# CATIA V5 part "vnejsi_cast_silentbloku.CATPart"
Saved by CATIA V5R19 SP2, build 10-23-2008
Part number: vnejsi_cast_silentbloku
Bounding box of the stored display mesh (mm): x -44.987 to 44.987, y -34 to 34, z -44.987 to 44.987
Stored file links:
  D:\Catia fórum\Modely - Otazky\Naklapeni_oprava\vnejsi_cast_silentbloku.CATPart
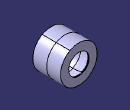
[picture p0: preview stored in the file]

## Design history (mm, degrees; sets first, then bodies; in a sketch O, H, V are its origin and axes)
Body1 (main body)
  Sketch1 on yz-plane, origin (0, 0, 0), H (0, 1, 0), V (0, 0, 1)
    axis line L1 (-49.7859, 0) -> (129.8264, 0)
    point P1 (-49.7859, 0)
    construction line L2 (0, 59.2551) -> (0, -50.8447)
    point P3 (0, 59.2551)
    line L3 (-34, 45) -> (0, 45)
    line L4 (-34, 45) -> (-34, 25)
    point P5 (-34, 45)
    arc A1 centre (0, 0) radius 40 from (0, 40) to (-30.3575, 26.0465) ccw
    point P6 (0, 40)
    point P7 (0, 45)
    line L5 (-34, 25) -> (-32.6343, 25)
    arc A2 centre (-32.6343, 28) radius 3 from (-30.3575, 26.0465) to (-32.6343, 25) cw
    point P8 (-30.3575, 26.0465)
    point P9 (-32.6343, 25)
    point P11 (-34, 25)
    point P12 (34, 45)
    point P13 (30.3575, 26.0465)
    point P14 (32.6343, 25)
    point P16 (34, 25)
    line L6 (34, 45) -> (34, 25)
    line L7 (34, 25) -> (32.6343, 25)
    arc A3 centre (32.6343, 28) radius 3 from (30.3575, 26.0465) to (32.6343, 25) ccw
    point P17 (0, 45)
    line L8 (34, 45) -> (0, 45)
    point P18 (0, 40)
    arc A4 centre (0, 0) radius 40 from (0, 40) to (30.3575, 26.0465) cw
    distance L3 L1 = 45
    distance L4 L2 = 34
    radius A1 = 40
    distance L5 L1 = 25
    radius A2 = 3
    coincidence: P1 H, P3 V, L2 P6, L2 P7, P6 P18, P7 P17
    horizontal: L1 H, L3 H, L5 H
    vertical: L2 V, L4 V
    tangency: A2 A1, A2 L5
    symmetry: P5 P12 L2, P8 P13 L2, P9 P14 L2, P11 P16 L2, L4 L6 L2, L5 L7 L2, A2 A3 L2, P7 P17 L2, L3 L8 L2, P6 P18 L2, A1 A4 L2
  Shaft1: profile Sketch1, axis Sketch1.L1, angle 360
